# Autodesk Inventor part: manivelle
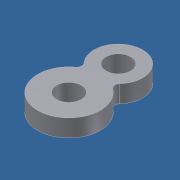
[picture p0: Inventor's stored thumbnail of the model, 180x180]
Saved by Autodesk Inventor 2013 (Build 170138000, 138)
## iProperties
Created: 2011-07
Part Number: manivelle
Document SubType Name: Modeling
Designer: Laur
Density: 7.85 g/cm^3
Material: Acier allié
Mass: 1.5824 g
Surface Area: 3.2003 cm^2
Volume: 0.20158 cm^3
Author: Laur
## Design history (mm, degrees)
sketch "Esquisse1"
  geometry: C1 r 1.77 at (0, 0); C2 r 1.77 at (0, 7.1); A1 r 3.5 centre (0, 7.1) between (2.573, 4.727) and (-2.573, 4.727); A2 r 4.5 centre (0, 0) between (-2.678, 3.616) and (2.678, 3.616); A3 r 0.75 centre (-3.124, 4.219) between (-2.678, 3.616) and (-2.573, 4.727); A4 r 0.75 centre (3.124, 4.219) between (2.573, 4.727) and (2.678, 3.616); 1 further point
  constraints: 8 point on circle, 6 centre point, 4 tangent, 3 coincident
  dimensions: "d0" = 9 diameter of A2; "d1" = 3.54 diameter of C1; "d2" = 3.54 diameter of C2 (= d1); "d3" = 7 diameter of A1; "d4" = 7.1 distance of point (0, 0) C2.centre; "d5" = 0 horizontal distance of C2.centre point (0, 0); "d6" = 1.5 diameter of A3; "d7" = 1.5 diameter of A4 (= d6)
extrude "formes dont Ø3,54" new body sketch "Esquisse1" distance "d8" = 2.5; taper "d9" = 0 deg
sketch "Esquisse2"
  geometry: L1 (0, 0)-(0, 27.555); C1 r 1.77 at (0, 7.1) reference; C2 r 1.77 at (0, 0) reference; A1 r 4.5 centre (0, 0) between (-2.678, 3.616) and (2.678, 3.616) reference; A2 r 0.75 centre (3.124, 4.219) between (2.573, 4.727) and (2.678, 3.616) reference; A3 r 3.5 centre (0, 7.1) between (2.573, 4.727) and (-2.573, 4.727) reference; A4 r 0.75 centre (-3.124, 4.219) between (-2.678, 3.616) and (-2.573, 4.727) reference
  constraints: 2 end point, 1 point on line
sketch "Esquisse3"
  geometry: L1 (0, 0)-(0, 7.1); C1 r 1.77 at (0, 7.1) reference; C2 r 1.77 at (0, 0) reference; A1 r 0.75 centre (-3.124, 4.219) between (-2.678, 3.616) and (-2.573, 4.727) reference; A2 r 4.5 centre (0, 0) between (-2.678, 3.616) and (2.678, 3.616) reference; A3 r 0.75 centre (3.124, 4.219) between (2.573, 4.727) and (2.678, 3.616) reference; A4 r 3.5 centre (0, 7.1) between (2.573, 4.727) and (-2.573, 4.727) reference
  constraints: 2 end point, 1 vertical
node "Solide1"
node "Corps solides"
node "Corps surfaciques"
